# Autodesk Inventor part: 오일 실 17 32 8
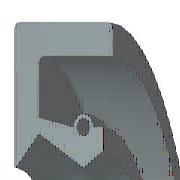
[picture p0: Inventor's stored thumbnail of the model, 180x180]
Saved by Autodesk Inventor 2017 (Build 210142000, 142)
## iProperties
IsCustomPart: 1
Created: 2012-02
Part Number: 오일 실 17 32 8
Material: 고무
Description: 오일-실
Document SubType Name: Modeling
Standard: KS B 2804
Designer: mduedu
Standards Organization: KS
Language: ko-KR
Size Designation: D - 17 32 8
Categories: <MemberInstance><Categories><Category DisplayName="샤프트 부품" InternalName="7f7aeb1f-a693-4053-b835-cee3144e0d98" Mnemonic="SHFT"><Category DisplayName="실링" Intern
Density: 0.93 g/cm^3
Appearance: 고무 - 검은색 - 버전 1.1
Author: mduedu
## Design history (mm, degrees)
revolve "본체" stored, may be unused: angle "d17" = 90 deg
revolve "스프링1" stored, may be unused: angle "d18" = 90 deg
body "Solid1"
sketch "스케치1"
  geometry: L1 (0, 16)-(8, 16); L2 (8, 14.25)-(1.75, 14.25); L3 (1.75, 10.25)-(4.9, 8.5); L4 (4.9, 8.5)-(0, 8.5); L5 (0, 0)-(9.586, 0) reference; L6 (4.9, 8.5)-(6.3, 9.375); L7 (0, 18)-(0, -3) reference; L8 (-1.941, 0)-(11.507, 0) reference; L9 (4.2, 10.6)-(1.75, 11.21); L10 (1.75, 11.21)-(1.75, 14.25); L11 (0, 16)-(0, 8.588); L12 (4.9, 8.5)-(0, 8.5); L13 (1.75, 10.25)-(0.152, 8.528); L14 (8, 16)-(8, 14.25); L15 (5.6, 10.6)-(6.3, 10.6); L16 (6.3, 10.6)-(6.3, 9.375); C1 r 0.455 at (4.9, 10.6); A1 r 0.7 centre (4.9, 10.6) between (5.6, 10.6) and (4.2, 10.6); A2 r 0.088 centre (0.088, 8.588) between (0, 8.588) and (0.152, 8.528); 1 further point
  constraints: 28 end point, 5 horizontal alignment, 5 point on line, 4 point on circle, 4 vertical alignment, 3 centre point, 3 tangent, 2 collinear, 2 horizontal, 2 perpendicular, 1 coincident, 1 parallel
  dimensions: "d0" = 32 diameter of L1 L5 (= SD2); "d1" = 1.75 distance of L1.end L2.start (= SD); "d2" = 0.91 diameter of C1 (= SPDI); "d3" = 1.4 diameter of A1 (= SPDA); "d4" = 17 diameter of L3.end L5 (= NND); "d5" = 20.5 diameter of L3.start L5 (= TKDM); "d7" = 22.42 diameter of L9.end L5 (= TKDM + 0.24 x SWDT); "d8" = 1.75 distance between parallel lines of L11 L10 (= SD); "d9" = 4.9 distance from line of L11 C1.centre (= SPDST); "d10" = 21.2 diameter of C1.centre L5 (= HLDM); "d11" = 0.0875 radius of A2 (= 0.25 x LAB); "d12" = 6.3 distance between parallel lines of L11 L16 (= SDI); "d13" = 18.75 diameter of L6.end L5 (= ABDM); "d14" = 8 distance from line of L11 L1.end (= SWDT)
fillet "모깎기1" dims "d6" = 0.3 (= RR)
other parameters: "SD2" = 32 [user parameter; used in 1 equation term], "SWDT" = 8 [user parameter; used in 2 equation terms], "RR" = 0.3 [user parameter; used in 1 equation term], "SD" = 1.75 [user parameter; used in 2 equation terms], "NND" = 17 [user parameter; used in 1 equation term], "SPDA" = 1.4 [user parameter; used in 1 equation term], "SPDI" = 0.91 [user parameter; used in 1 equation term], "TKDM" = 20.5 [user parameter; used in 2 equation terms], "HLDM" = 21.2 [user parameter; used in 1 equation term], "ABDM" = 18.75 [user parameter; used in 1 equation term], "SDI" = 6.3 [user parameter; used in 1 equation term], "SPDST" = 4.9 [user parameter; used in 1 equation term], "LAB" = 0.35 [user parameter; used in 1 equation term], "d15" = 0, "d16" = 0, "d19" = 0
